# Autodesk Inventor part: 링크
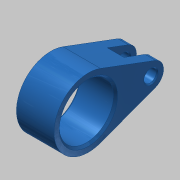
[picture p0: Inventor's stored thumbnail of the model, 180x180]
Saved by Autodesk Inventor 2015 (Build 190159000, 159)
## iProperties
Created: 2016-08
Part Number: 링크
Material: 강철, 탄소
Document SubType Name: Modeling
Designer: mduedu
Density: 7.87 g/cm^3
Appearance: 청록색
Mass: 80.4021 g
Surface Area: 54.1946 cm^2
Volume: 10.2163 cm^3
Author: mduedu
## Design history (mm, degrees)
sketch "스케치1"
  geometry: L1 (32.1, 5.62)-(5.775, 15.456); L2 (32.1, -5.62)-(5.775, -15.456); C1 r 13 at (0, 0); C2 r 3 at (30, 0); A1 r 16.5 centre (0, 0) between (5.775, 15.456) and (5.775, -15.456); A2 r 6 centre (30, 0) between (32.1, 5.62) and (32.1, -5.62); 1 further point
  constraints: 4 centre point, 4 end point, 4 point on circle, 4 tangent, 3 coincident, 1 horizontal alignment
  dimensions: "d0" = 33 diameter of A1; "d2" = 12 diameter of A2; "d3" = 30 distance of A2.centre point (0, 0); "d4" = 26 diameter of C1; "d5" = 6 diameter of C2
extrude "돌출1" new body sketch "스케치1" stored distance "d6" = 18; taper "d7" = 0 deg
sketch "스케치2"
  geometry: L1 (-9, 36)-(9, 36) reference; L2 (0, 0)-(0, 36); L3 (-4, 36)-(4, 36); L4 (4, 36)-(4, 22); L5 (4, 22)-(-4, 22); L6 (-4, 22)-(-4, 36)
  constraints: 10 end point, 2 midpoint, 2 parallel, 1 horizontal, 1 perpendicular, 1 point on line
  dimensions: "d8" = 8 distance between parallel lines of L4 L6; "d10" = 14 distance of L3.end L4.end
extrude "돌출2" cut sketch "스케치2" stored distance "d11" = 20; taper "d12" = 0 deg
chamfer "모따기1" distance "d13" = 1; stored, may be unused: second distance "d14" = 2, angle "d15" = 45 deg
chamfer "모따기2" distance "d16" = 0.5; stored, may be unused: second distance "d17" = 2, angle "d18" = 45 deg
node "솔리드1"
